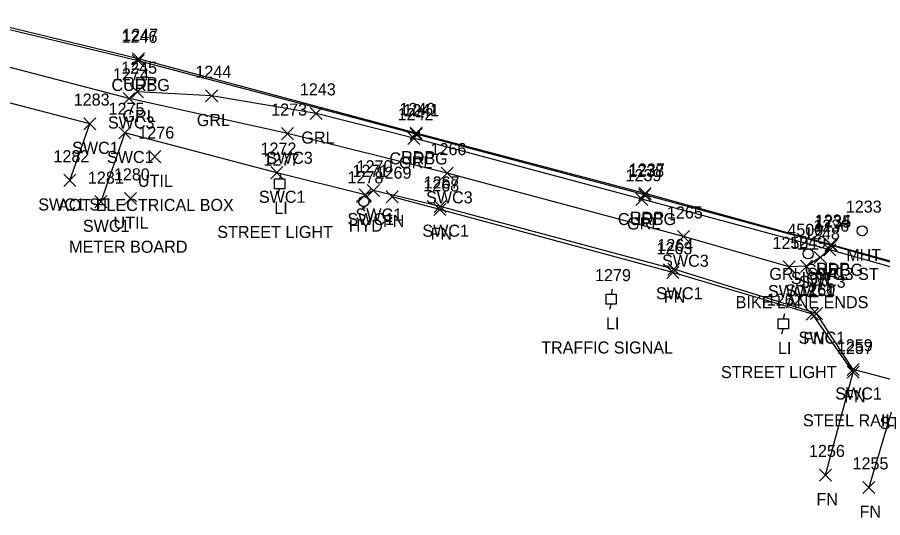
# Model space of a CAD drawing. Extents: x 1690689 to 1696275, y 438760 to 444007.
# Drawn here: x 1692953 to 1693096.4, y 438759.8 to 438842.7 of the extents above; entities that cross this region are included whole.
import ezdxf

# ---------------------------------------------------------------- set-up
doc = ezdxf.new("R2010")
doc.units = 0
for name, color, linetype in [('L_A', 7, 'Continuous'), ('L_C', 7, 'Continuous'), ('L_I', 7, 'Continuous'), ('L_TIC', 7, 'Continuous'), ('LFNC', 7, 'Continuous'), ('P_A', 7, 'Continuous'), ('P_I', 7, 'Continuous'), ('P_TIC', 7, 'Continuous'), ('PET', 7, 'Continuous'), ('R_A', 7, 'Continuous'), ('R_I', 7, 'Continuous'), ('R_TIC', 7, 'Continuous'), ('RC', 7, 'Continuous'), ('RGR', 7, 'Continuous'), ('RSW', 7, 'Continuous'), ('S_A', 7, 'Continuous'), ('S_C', 7, 'Continuous'), ('S_I', 7, 'Continuous'), ('SSGN', 7, 'Continuous'), ('U_A', 7, 'Continuous'), ('U_C', 7, 'Continuous'), ('U_I', 7, 'Continuous'), ('UDEFAULT', 7, 'Continuous'), ('ULP', 7, 'Continuous'), ('UTMH', 7, 'Continuous'), ('UWFH', 7, 'Continuous')]:
    doc.layers.add(name, color=color, linetype=linetype)

msp = doc.modelspace()

# ---------------------------------------------------------------- linework, layer by layer
at = {"layer": 'L_TIC'}
for points in [[(1693014.13, 438811.98), (1693016.13, 438813.98)], [(1693016.13, 438811.98), (1693014.13, 438813.98)], [(1693022.03, 438809.87), (1693024.03, 438811.87)], [(1693024.03, 438809.87), (1693022.03, 438811.87)], [(1693060.67, 438799.44), (1693062.67, 438801.44)], [(1693062.67, 438799.44), (1693060.67, 438801.44)], [(1693083.77, 438792.51), (1693085.77, 438794.51)], [(1693085.77, 438792.51), (1693083.77, 438794.51)], [(1693090.54, 438782.92), (1693092.54, 438784.92)], [(1693092.54, 438782.92), (1693090.54, 438784.92)], [(1693085.96, 438765.84), (1693087.96, 438767.84)], [(1693087.96, 438765.84), (1693085.96, 438767.84)], [(1693093.12, 438763.77), (1693095.12, 438765.77)], [(1693095.12, 438763.77), (1693093.12, 438765.77)]]:
    msp.add_lwpolyline(points, dxfattribs=at)
at = {"layer": 'LFNC'}
for points in [[(1693086.96, 438766.84), (1693091.54, 438783.92), (1693084.77, 438793.51), (1693061.67, 438800.44), (1693023.03, 438810.87), (1693015.13, 438812.98)], [(1693110.15, 438782.12), (1693104.26, 438783.48), (1693099.18, 438781.71), (1693094.12, 438764.77)]]:
    msp.add_lwpolyline(points, dxfattribs=at)
at = {"layer": 'P_TIC'}
for points in [[(1692972.09, 438834.84), (1692974.09, 438836.84)], [(1692974.09, 438834.84), (1692972.09, 438836.84)], [(1693018.12, 438822.55), (1693020.12, 438824.55)], [(1693020.12, 438822.55), (1693018.12, 438824.55)], [(1693056.06, 438812.51), (1693058.06, 438814.51)], [(1693058.06, 438812.51), (1693056.06, 438814.51)], [(1693086.86, 438804.04), (1693088.86, 438806.04)], [(1693088.86, 438804.04), (1693086.86, 438806.04)]]:
    msp.add_lwpolyline(points, dxfattribs=at)
at = {"layer": 'PET'}
msp.add_lwpolyline([(1693167.67, 438782.57), (1693141.53, 438790.2), (1693112.15, 438798.3), (1693087.86, 438805.04), (1693057.06, 438813.51), (1693019.12, 438823.55), (1692973.09, 438835.84), (1692924.99, 438847.57), (1692878.5, 438859.29), (1692838.41, 438869.51), (1692796.94, 438879.76), (1692752.35, 438890.07), (1692731.67, 438894.52), (1692658.1, 438910.21), (1692638.65, 438914.4), (1692605.27, 438921.45), (1692561.1, 438930.73), (1692527.61, 438937.28), (1692485.07, 438945.57), (1692435.03, 438955.4)], dxfattribs=at)
at = {"layer": 'R_TIC'}
for points in [[(1692972.04, 438834.52), (1692974.04, 438836.52)], [(1692974.04, 438834.52), (1692972.04, 438836.52)], [(1692971.92, 438829.39), (1692973.92, 438831.39)], [(1692973.92, 438829.39), (1692971.92, 438831.39)], [(1692970.56, 438828.3), (1692972.56, 438830.3)], [(1692972.56, 438828.3), (1692970.56, 438830.3)], [(1692984.22, 438828.71), (1692986.22, 438830.71)], [(1692986.22, 438828.71), (1692984.22, 438830.71)], [(1693001.54, 438825.8), (1693003.54, 438827.8)], [(1693003.54, 438825.8), (1693001.54, 438827.8)], [(1692964.05, 438824.1), (1692966.05, 438826.1)], [(1692966.05, 438824.1), (1692964.05, 438826.1)], [(1692969.83, 438822.58), (1692971.83, 438824.58)], [(1692971.83, 438822.58), (1692969.83, 438824.58)], [(1692996.77, 438822.45), (1692998.77, 438824.45)], [(1692998.77, 438822.45), (1692996.77, 438824.45)], [(1693018.1, 438822.35), (1693020.1, 438824.35)], [(1693020.1, 438822.35), (1693018.1, 438824.35)], [(1693017.73, 438821.68), (1693019.73, 438823.68)], [(1693019.73, 438821.68), (1693017.73, 438823.68)], [(1692995.01, 438815.98), (1692997.01, 438817.98)], [(1692997.01, 438815.98), (1692995.01, 438817.98)], [(1693023.27, 438815.89), (1693025.27, 438817.89)], [(1693025.27, 438815.89), (1693023.27, 438817.89)], [(1692960.7, 438814.71), (1692962.7, 438816.71)], [(1692962.7, 438814.71), (1692960.7, 438816.71)], [(1693009.68, 438812.29), (1693011.68, 438814.29)], [(1693011.68, 438812.29), (1693009.68, 438814.29)], [(1693011.02, 438813.04), (1693013.02, 438815.04)], [(1693013.02, 438813.04), (1693011.02, 438815.04)], [(1693055.95, 438812.29), (1693057.95, 438814.29)], [(1693057.95, 438812.29), (1693055.95, 438814.29)], [(1692965.84, 438811.17), (1692967.84, 438813.17)], [(1692967.84, 438811.17), (1692965.84, 438813.17)], [(1693055.51, 438811.56), (1693057.51, 438813.56)], [(1693057.51, 438811.56), (1693055.51, 438813.56)], [(1693022.1, 438810.36), (1693024.1, 438812.36)], [(1693024.1, 438810.36), (1693022.1, 438812.36)], [(1693062.4, 438805.38), (1693064.4, 438807.38)], [(1693064.4, 438805.38), (1693062.4, 438807.38)], [(1693086.95, 438803.88), (1693088.95, 438805.88)], [(1693088.95, 438803.88), (1693086.95, 438805.88)], [(1693085.09, 438801.9), (1693087.09, 438803.9)], [(1693087.09, 438801.9), (1693085.09, 438803.9)], [(1693086.68, 438803.2), (1693088.68, 438805.2)], [(1693088.68, 438803.2), (1693086.68, 438805.2)], [(1693086.68, 438803.2), (1693088.68, 438805.2)], [(1693088.68, 438803.2), (1693086.68, 438805.2)], [(1693082.8, 438800.45), (1693084.8, 438802.45)], [(1693084.8, 438800.45), (1693082.8, 438802.45)], [(1693060.82, 438799.98), (1693062.82, 438801.98)], [(1693062.82, 438799.98), (1693060.82, 438801.98)], [(1693079.94, 438800.34), (1693081.94, 438802.34)], [(1693081.94, 438800.34), (1693079.94, 438802.34)], [(1693084.44, 438792.62), (1693086.44, 438794.62)], [(1693086.44, 438792.62), (1693084.44, 438794.62)], [(1693090.52, 438783.36), (1693092.52, 438785.36)], [(1693092.52, 438783.36), (1693090.52, 438785.36)]]:
    msp.add_lwpolyline(points, dxfattribs=at)
at = {"layer": 'RC'}
msp.add_lwpolyline([(1693167.44, 438782.14), (1693141.42, 438789.93), (1693119.24, 438796.02), (1693112.17, 438798), (1693087.95, 438804.88), (1693056.95, 438813.29), (1693019.1, 438823.35), (1692973.04, 438835.52), (1692925.29, 438847.1), (1692878.46, 438858.86), (1692838.19, 438869.18), (1692796.47, 438878.9), (1692752.32, 438889.87), (1692731.59, 438894.27), (1692657.89, 438909.92), (1692639.33, 438913.93), (1692605.34, 438921.22), (1692561.27, 438930.49), (1692527.54, 438937.1), (1692485.06, 438945.4), (1692435.02, 438955.15)], dxfattribs=at)
at = {"layer": 'RGR'}
msp.add_lwpolyline([(1693167.24, 438781.7), (1693141.39, 438789.13), (1693119.01, 438795.42), (1693111.87, 438797.41), (1693087.68, 438804.2), (1693056.51, 438812.56), (1693018.73, 438822.68), (1693002.54, 438826.8), (1692985.22, 438829.71), (1692972.92, 438830.39)], dxfattribs=at)
at = {"layer": 'RSW'}
for points in [[(1692961.7, 438815.71), (1692965.05, 438825.1), (1692922.46, 438836.11), (1692875.99, 438847.64), (1692836.17, 438857.54), (1692822.55, 438868.12), (1692796.53, 438874.61), (1692766.39, 438881.99), (1692766.23, 438881.85), (1692750.5, 438885.32), (1692729.84, 438889.75), (1692656.64, 438905.41), (1692656.72, 438906.14), (1692638.39, 438910.1), (1692639.33, 438913.93)], [(1693087.68, 438804.2), (1693086.09, 438802.9), (1693083.8, 438801.45), (1693080.94, 438801.34), (1693063.4, 438806.38), (1693024.27, 438816.89), (1692997.77, 438823.45), (1692971.56, 438829.3), (1692923.99, 438841.68), (1692877.37, 438853.2), (1692839, 438862.94), (1692837.89, 438864.26), (1692838.06, 438868.91)], [(1693166.44, 438776.01), (1693162.84, 438776.9), (1693155.45, 438778.77), (1693139.96, 438781.48), (1693127.99, 438782.57), (1693119.97, 438782.67), (1693115.52, 438782.45), (1693110.59, 438782.37), (1693104.44, 438783.96), (1693099.72, 438782.2), (1693091.52, 438784.36), (1693085.44, 438793.62), (1693061.82, 438800.98), (1693023.1, 438811.36), (1693012.02, 438814.04), (1693010.68, 438813.29), (1692996.01, 438816.98), (1692970.83, 438823.58), (1692966.84, 438812.17)]]:
    msp.add_lwpolyline(points, dxfattribs=at)
at = {"layer": 'SSGN'}
for p, q in [((1693082.42, 438804.36), (1693085.75, 438804.36)), ((1693084.07, 438803.53), (1693084.07, 438803.53))]:
    msp.add_line(p, q, dxfattribs=at)
msp.add_circle((1693084.07, 438803.53), 0.833, dxfattribs=at)
at = {"layer": 'UDEFAULT'}
for points in [[(1692974.82, 438818.63), (1692976.82, 438820.63)], [(1692976.82, 438818.63), (1692974.82, 438820.63)], [(1692970.79, 438811.7), (1692972.79, 438813.7)], [(1692972.79, 438811.7), (1692970.79, 438813.7)]]:
    msp.add_lwpolyline(points, dxfattribs=at)
at = {"layer": 'ULP'}
for p, q in [((1692996.66, 438816.82), (1692996.49, 438815.98)), ((1692995.66, 438814.32), (1692995.66, 438815.98)), ((1692995.66, 438815.98), (1692997.33, 438815.98)), ((1692997.33, 438815.98), (1692997.33, 438814.32)), ((1692997.33, 438814.32), (1692995.66, 438814.32)), ((1692996.24, 438813.48), (1692996.49, 438814.32)), ((1692996.49, 438815.15), (1692996.49, 438815.15)), ((1693050.62, 438795.16), (1693050.62, 438796.83)), ((1693050.62, 438796.83), (1693052.28, 438796.83)), ((1693051.62, 438797.66), (1693051.45, 438796.83)), ((1693052.28, 438796.83), (1693052.28, 438795.16)), ((1693051.45, 438795.99), (1693051.45, 438795.99)), ((1693052.28, 438795.16), (1693050.62, 438795.16)), ((1693051.2, 438794.33), (1693051.45, 438795.16)), ((1693079.13, 438791.09), (1693079.13, 438792.76)), ((1693079.13, 438792.76), (1693080.79, 438792.76)), ((1693080.13, 438793.59), (1693079.96, 438792.76)), ((1693080.79, 438792.76), (1693080.79, 438791.09)), ((1693080.79, 438791.09), (1693079.13, 438791.09)), ((1693079.71, 438790.26), (1693079.96, 438791.09)), ((1693079.96, 438791.92), (1693079.96, 438791.92))]:
    msp.add_line(p, q, dxfattribs=at)
at = {"layer": 'UTMH'}
for p, q in [((1693093.01, 438807.35), (1693093.01, 438807.35)), ((1693093.84, 438807.35), (1693093.84, 438807.35))]:
    msp.add_line(p, q, dxfattribs=at)
msp.add_circle((1693093.01, 438807.35), 0.833, dxfattribs=at)
at = {"layer": 'UWFH'}
msp.add_line((1693010.43, 438812.2), (1693010.43, 438812.2), dxfattribs=at)
for centre, radius in [((1693010.43, 438812.2), 0.833), ((1693009.43, 438812.2), 0.167), ((1693010.43, 438811.2), 0.167), ((1693011.43, 438812.2), 0.167)]:
    msp.add_circle(centre, radius, dxfattribs=at)

# ---------------------------------------------------------------- texts
at = {"layer": 'L_A'}
for p in [(1693013.61, 438807.98), (1693021.51, 438805.87), (1693060.15, 438795.44), (1693083.25, 438788.51), (1693090.02, 438778.92), (1693085.44, 438761.84), (1693092.6, 438759.77)]:
    msp.add_text('FN', height=2, dxfattribs=at).set_placement(p)
at = {"layer": 'L_C'}
for p in [(1693083.21, 438774.92), (1693095.93, 438774.48)]:
    msp.add_text('STEEL RAIL', height=2, dxfattribs=at).set_placement(p)
at = {"layer": 'L_I'}
for s, p in [('1269', (1693012.39, 438815.98)), ('1268', (1693020.29, 438813.87)), ('1263', (1693058.93, 438803.44)), ('1261', (1693082.6, 438796.51)), ('1257', (1693088.85, 438786.92)), ('1256', (1693084.21, 438769.84)), ('1255', (1693091.43, 438767.77))]:
    msp.add_text(s, height=2, dxfattribs=at).set_placement(p)
at = {"layer": 'P_A'}
for p in [(1692970.58, 438830.84), (1693016.61, 438818.55), (1693054.55, 438808.51), (1693085.35, 438800.04)]:
    msp.add_text('RDP', height=2, dxfattribs=at).set_placement(p)
at = {"layer": 'P_I'}
for s, p in [('1247', (1692970.4, 438838.84)), ('1240', (1693016.34, 438826.55)), ('1237', (1693054.37, 438816.51)), ('1234', (1693085.17, 438808.04))]:
    msp.add_text(s, height=2, dxfattribs=at).set_placement(p)
at = {"layer": 'R_A'}
for s, p in [('CURBG', (1692968.62, 438830.52)), ('GRL', (1692970.46, 438825.39)), ('SWC3', (1692968.03, 438824.3)), ('GRL', (1692982.76, 438824.71)), ('GRL', (1693000.08, 438821.8)), ('SWC1', (1692962.09, 438820.1)), ('SWC1', (1692967.87, 438818.58)), ('SWC3', (1692994.25, 438818.45)), ('CURBG', (1693014.68, 438818.35)), ('GRL', (1693016.27, 438817.68)), ('SWC1', (1692993.05, 438811.98)), ('SWC3', (1693020.75, 438811.89)), ('SWC1 ST', (1692956.48, 438810.71)), ('SWC1', (1693009.06, 438809.04)), ('SWC1', (1693007.72, 438808.29)), ('CURBG', (1693052.53, 438808.29)), ('GRL', (1693054.05, 438807.56)), ('SWC1', (1692963.88, 438807.17)), ('SWC1', (1693020.14, 438806.36)), ('SWC3', (1693059.87, 438801.38)), ('GRL SWC3 ST', (1693077.64, 438799.2)), ('CURBG', (1693083.53, 438799.88)), ('GRL', (1693085.22, 438799.2)), ('SWC3', (1693082.56, 438797.9)), ('SWC3', (1693077.41, 438796.34)), ('SWC3', (1693080.28, 438796.45)), ('SWC1', (1693058.86, 438795.98)), ('SWC1', (1693082.48, 438788.62)), ('SWC1', (1693088.56, 438779.36))]:
    msp.add_text(s, height=2, dxfattribs=at).set_placement(p)
at = {"layer": 'R_I'}
for s, p in [('1246', (1692970.29, 438838.52)), ('1245', (1692970.22, 438833.39)), ('1274', (1692968.87, 438832.3)), ('1244', (1692982.52, 438832.71)), ('1243', (1692999.84, 438829.8)), ('1283', (1692962.36, 438828.1)), ('1275', (1692968.14, 438826.58)), ('1273', (1692995.08, 438826.45)), ('1241', (1693016.97, 438826.35)), ('1242', (1693016.04, 438825.68)), ('1272', (1692993.32, 438819.98)), ('1266', (1693021.48, 438819.89)), ('1282', (1692959, 438818.71)), ('1271', (1693008.55, 438816.29)), ('1270', (1693009.24, 438817.04)), ('1238', (1693054.25, 438816.29)), ('1281', (1692964.71, 438815.17)), ('1239', (1693053.81, 438815.56)), ('1267', (1693020.36, 438814.36)), ('1265', (1693060.66, 438809.38)), ('1235', (1693085.26, 438807.88)), ('1236', (1693084.93, 438807.2)), ('1236', (1693084.93, 438807.2)), ('1248', (1693083.39, 438805.9)), ('1264', (1693059.08, 438803.98)), ('1250', (1693078.16, 438804.34)), ('1249', (1693081.1, 438804.45)), ('1260', (1693082.61, 438796.62)), ('1259', (1693088.82, 438787.36))]:
    msp.add_text(s, height=2, dxfattribs=at).set_placement(p)
at = {"layer": 'S_A'}
msp.add_text('SIGN', height=2, dxfattribs=at).set_placement((1693081.21, 438798.51))
at = {"layer": 'S_C'}
msp.add_text('BIKE LANE ENDS', height=2, dxfattribs=at).set_placement((1693072.06, 438794.51))
at = {"layer": 'S_I'}
msp.add_text('4500', height=2, dxfattribs=at).set_placement((1693080.62, 438806.51))
at = {"layer": 'U_A'}
for s, p in [('UTIL', (1692972.99, 438814.63)), ('LI', (1692995.59, 438810.15)), ('UTIL', (1692968.96, 438807.7)), ('HYD', (1693007.95, 438807.2)), ('MHT', (1693090.38, 438802.35)), ('LI', (1693050.55, 438790.99)), ('LI', (1693079.06, 438786.92))]:
    msp.add_text(s, height=2, dxfattribs=at).set_placement(p)
at = {"layer": 'U_C'}
for s, p in [('AOT ELECTRICAL BOX', (1692959.76, 438810.63)), ('STREET LIGHT', (1692986.15, 438806.15)), ('METER BOARD', (1692961.6, 438803.7)), ('TRAFFIC SIGNAL', (1693039.83, 438786.99)), ('STREET LIGHT', (1693069.62, 438782.92))]:
    msp.add_text(s, height=2, dxfattribs=at).set_placement(p)
at = {"layer": 'U_I'}
for s, p in [('1276', (1692973.07, 438822.63)), ('1277', (1692993.8, 438818.15)), ('1280', (1692969.02, 438815.7)), ('1278', (1693007.73, 438815.2)), ('1233', (1693090.31, 438810.35)), ('1279', (1693048.75, 438798.99)), ('1262', (1693077.22, 438794.92))]:
    msp.add_text(s, height=2, dxfattribs=at).set_placement(p)

doc.saveas('drawing.dxf')
